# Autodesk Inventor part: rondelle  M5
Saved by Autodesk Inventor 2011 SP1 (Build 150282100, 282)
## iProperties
Created: 2010-12
Part Number: rondelle  M5
Document SubType Name: Modeling
Designer: eric
Density: 1 g/cm^3
Mass: 0.0910355 g
Surface Area: 2.36421 cm^2
Volume: 0.0910355 cm^3
Author: eric
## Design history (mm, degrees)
feature "Base1"
node "Solide1"
node "Corps solides"
node "Corps surfaciques"
